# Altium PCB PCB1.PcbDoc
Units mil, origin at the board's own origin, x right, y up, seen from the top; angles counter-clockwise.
Board outline 4025 x 3055 mil, 2 copper layers (Top Layer, Bottom Layer); 6 components, 13 nets, 109 pads, 0 vias.
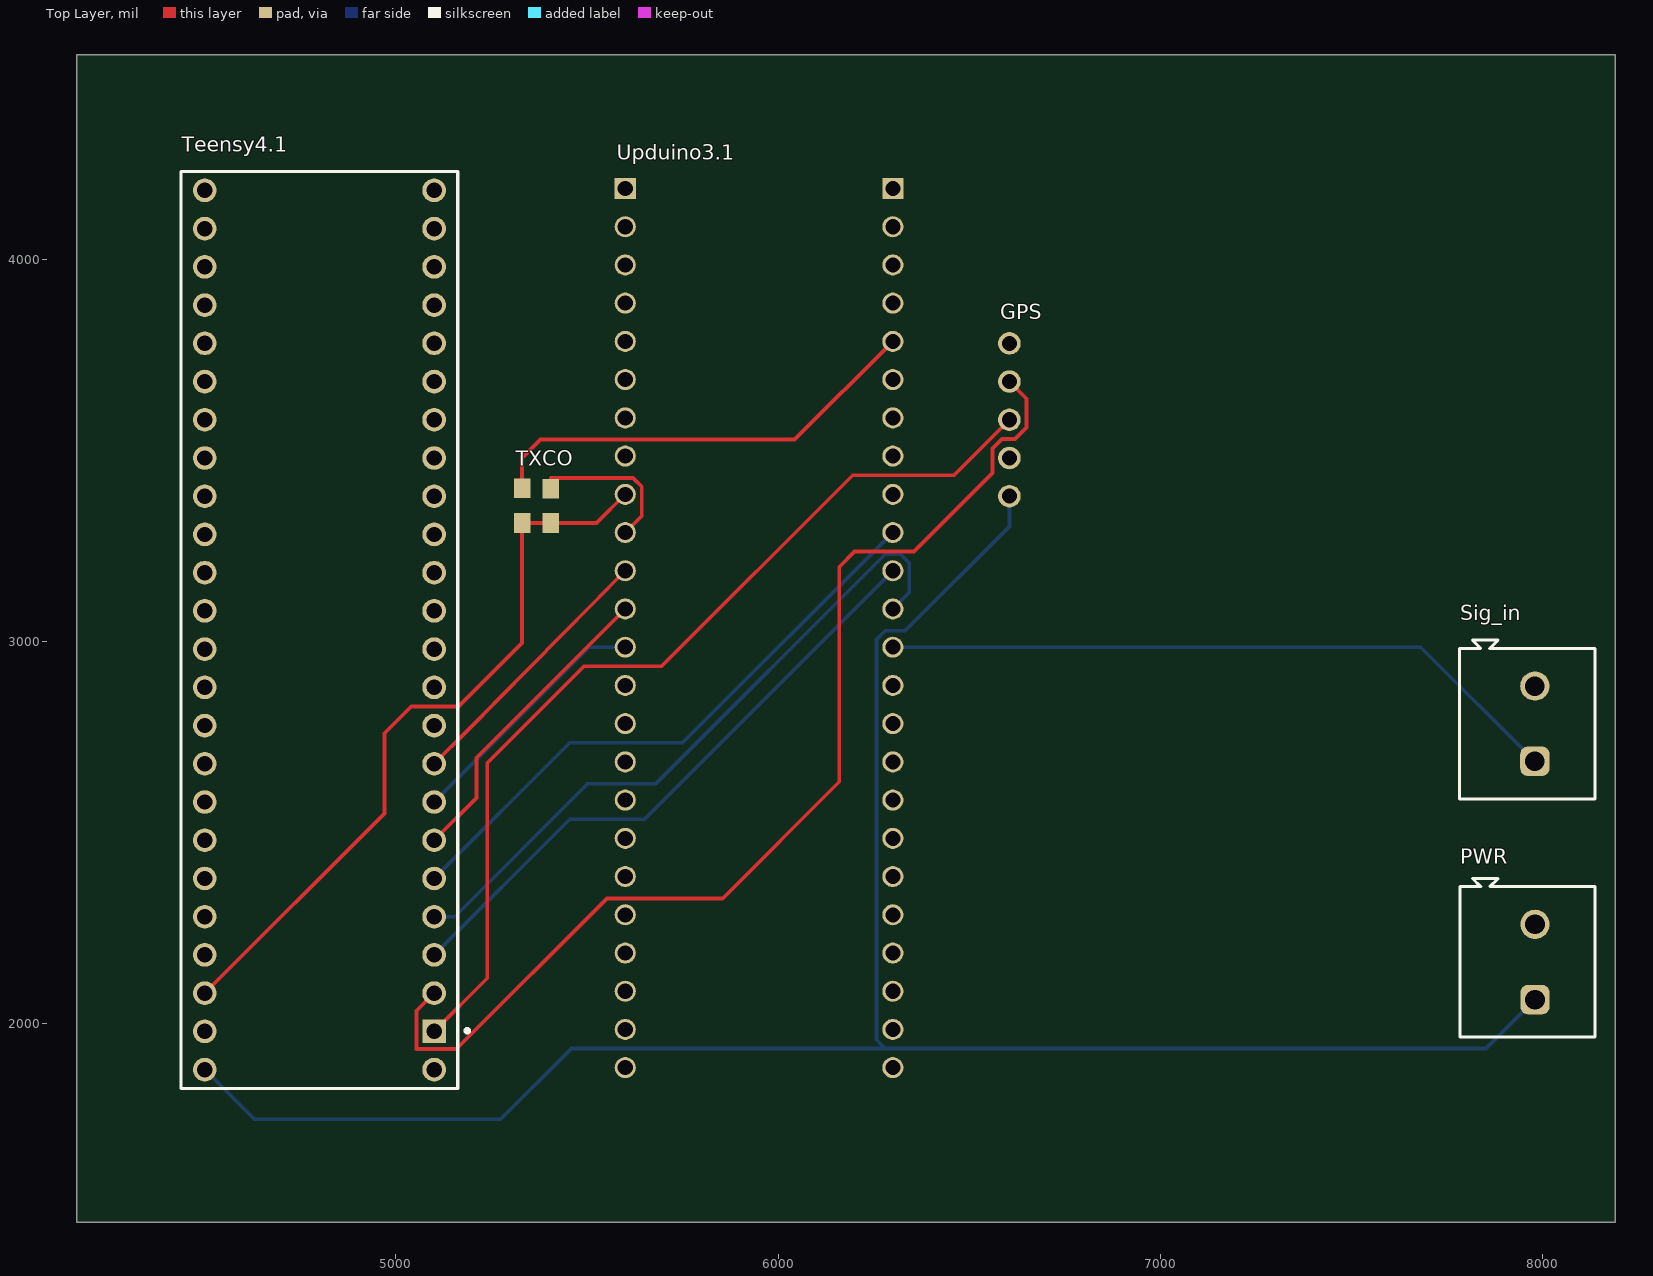
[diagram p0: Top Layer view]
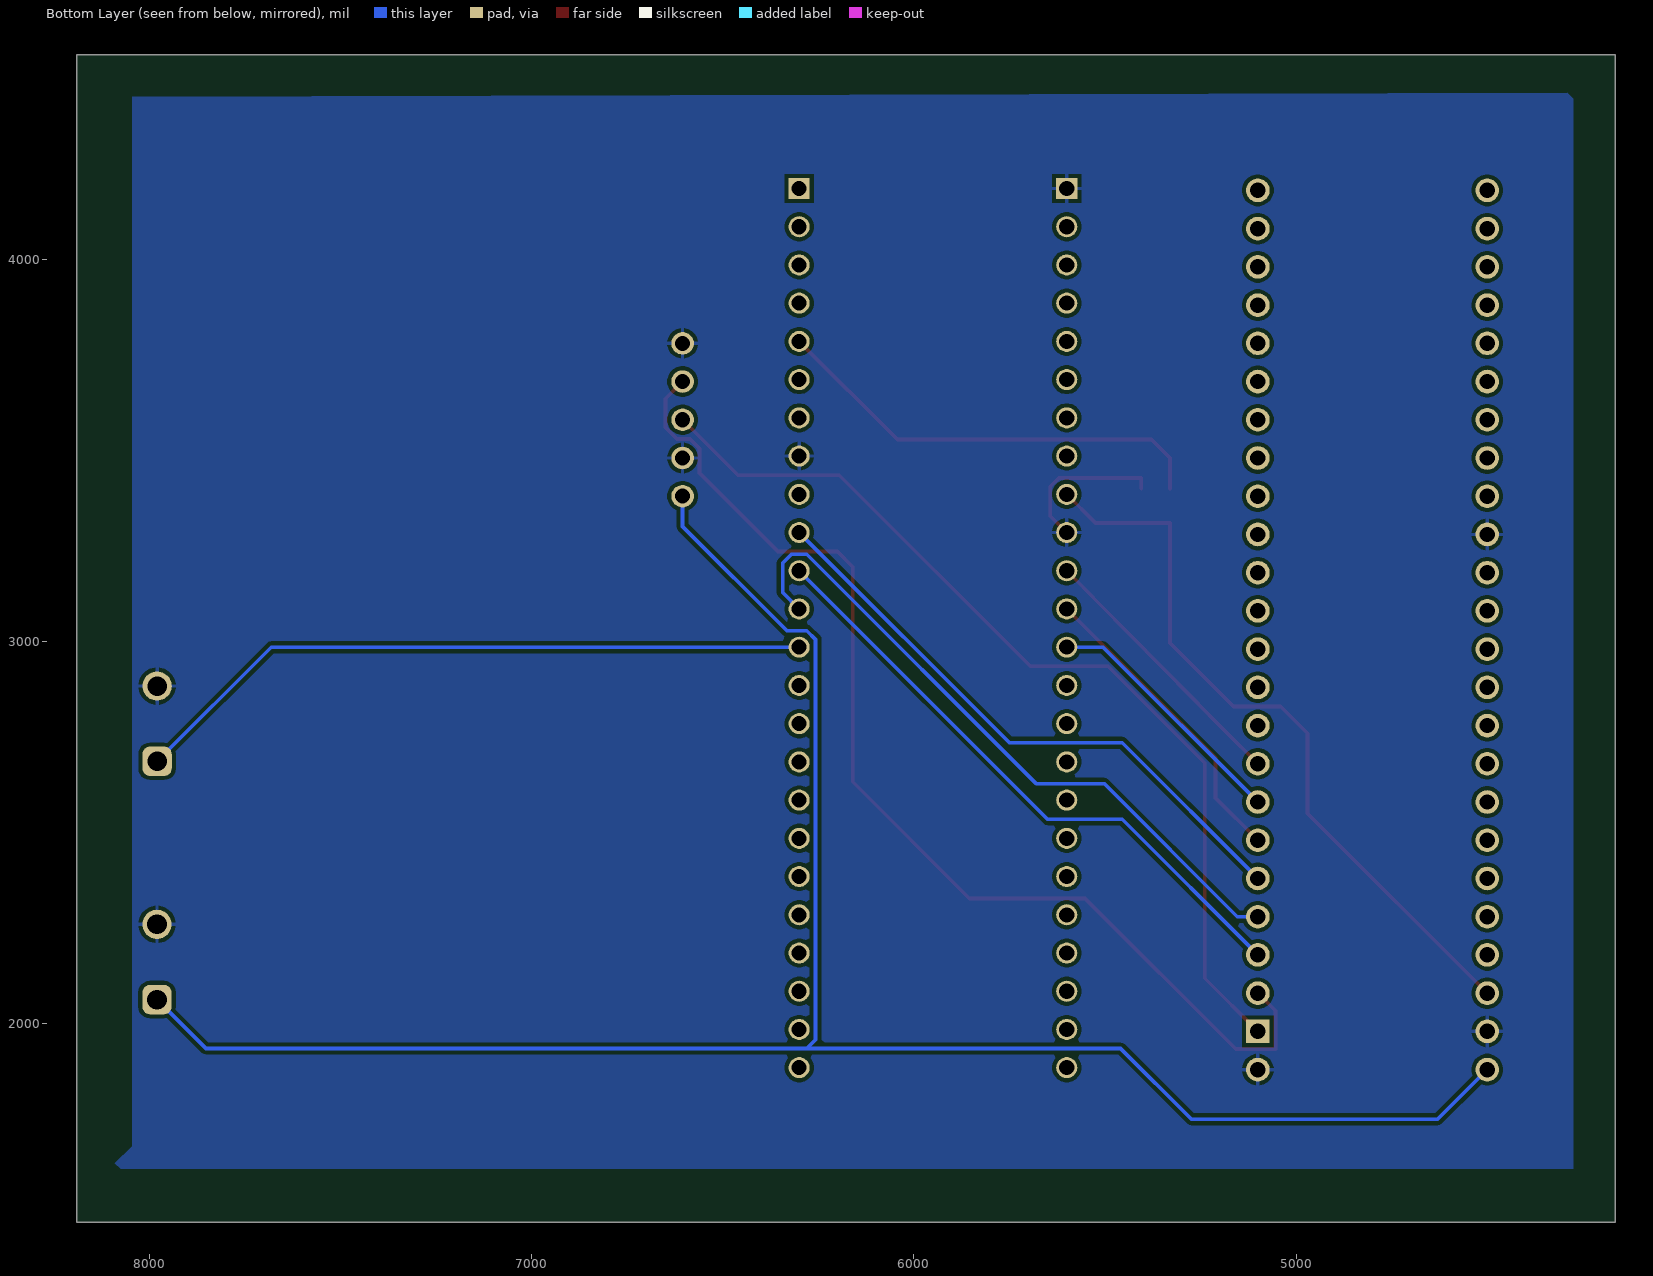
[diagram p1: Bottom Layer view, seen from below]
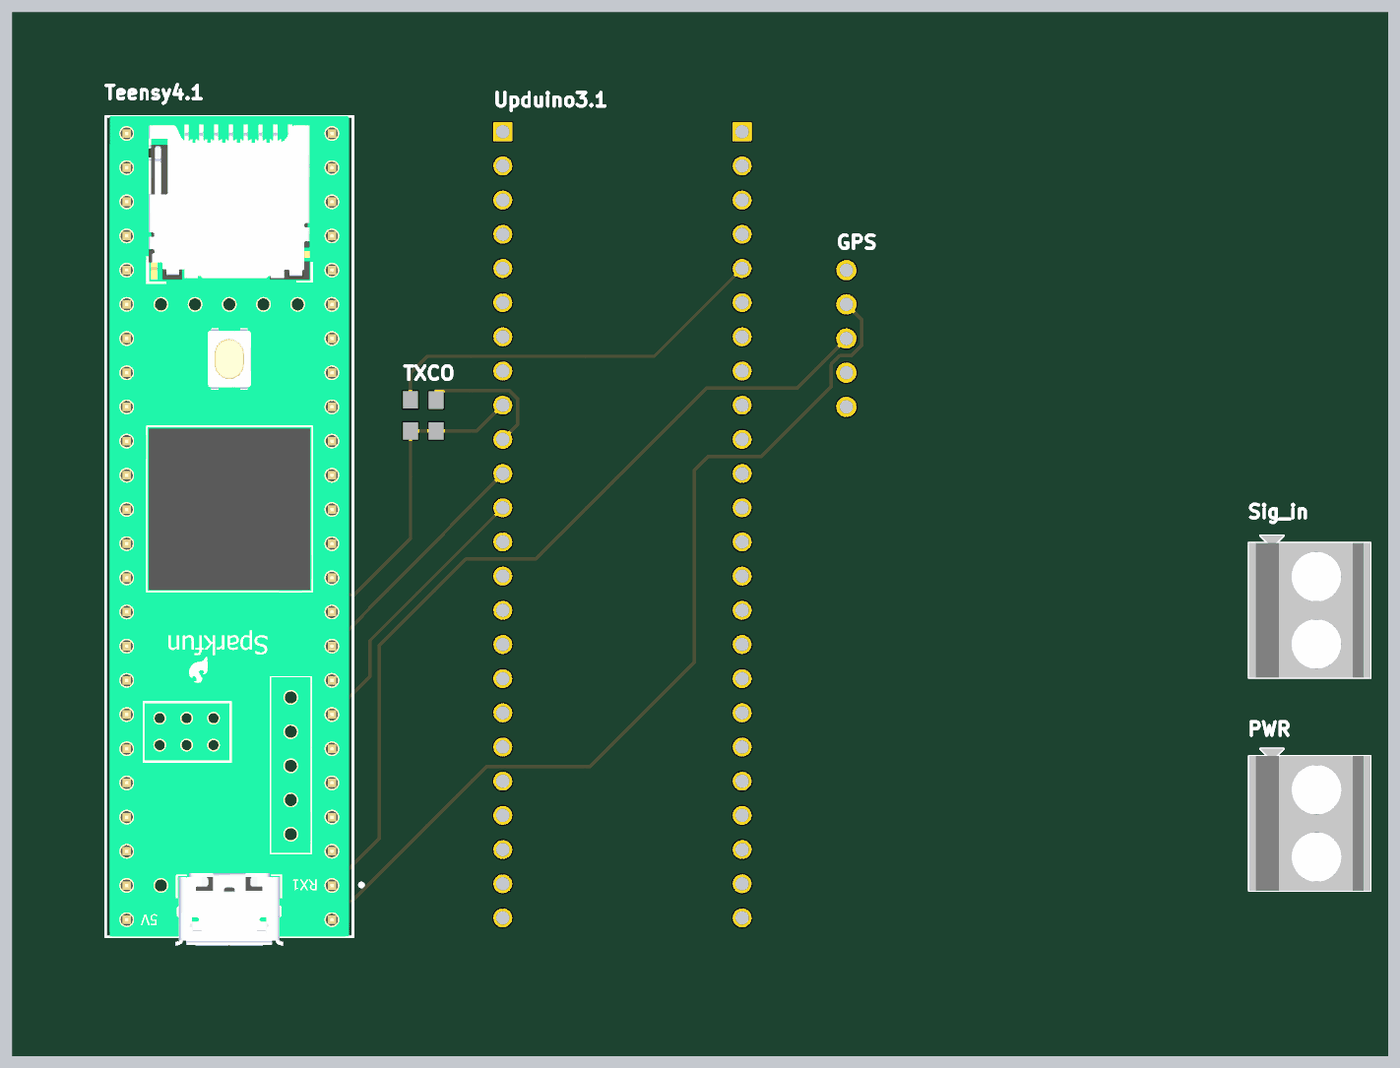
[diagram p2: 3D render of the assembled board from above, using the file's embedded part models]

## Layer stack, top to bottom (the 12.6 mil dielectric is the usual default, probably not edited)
Top Solder: solder mask 0.4, Solder Resist, Dk 3.5
Top Layer: signal copper 1.4
Dielectric 1: dielectric 12.6, FR-4, Dk 4.8
Bottom Layer: signal copper 1.4
Bottom Solder: solder mask 0.4, Solder Resist, Dk 3.5

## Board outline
4165,1480 8190,1480 8190,4535 4165,4535

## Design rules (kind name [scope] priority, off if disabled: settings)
Clearance [All] p1: gap=10 ignorepadtopadclearanceinfootprint=FALSE
PolygonConnect [All] p1: connectstyle=Relief reliefconductorwidth=10 reliefentries=4 polygonreliefangle="90 Angle" airgapwidth=10
RoutingVias [All] p1: holewidth=28 width=50 viastyle="Through Hole" minholewidth=28 minwidth=50 maxholewidth=28 maxwidth=50
SolderMaskExpansion [All] p1: expansion=4 istentingtop=FALSE
Width [All] p1: maxlimit=10 minlimit=10 preferedwidth=10
30 further rules are at their usual default settings.

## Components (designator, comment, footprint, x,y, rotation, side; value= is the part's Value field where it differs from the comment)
GPS "GPS_Module" GPS 6605,3380 r0 top
PWR "691134710002" 691134710002 7960.31,2161.57 r90 top
Sig_in "691134710002" 691134710002 7960,2785 r90 top
Teensy4.1 "DEV-16996" FP-DEV-16996-MFG 4800,3030 r90 top
TXCO "TXCO Clock" "TXCO CLOCK" 5405,3310 r90 top
Upduino3.1 "FPGA" UPDUINOV3.1 5600,1885 r0 top

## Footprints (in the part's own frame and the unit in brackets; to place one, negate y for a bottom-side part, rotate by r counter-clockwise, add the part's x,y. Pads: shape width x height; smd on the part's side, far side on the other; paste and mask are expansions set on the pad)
691134710002 [mm] "Serie 1347 - 5.00 mm_2 pins"
  rrect50% 1.95x1.95 hole 1.3: 1(-2.5,-0.5)
  round 1.95 hole 1.3: 2(2.5,-0.5)
  silkscreen extent -5,-4.5 5.55,4.5, body extent -5,-4.5 5.55,4.5, height 13.1
FP-DEV-16996-MFG [mm]
  rect 1.57x1.57 hole 1.02 paste-2539.97 mask+0: 0(-26.67,-7.62)
  round 1.57 hole 1.02 paste-2539.97 mask+0: 1(-24.13,-7.62) 2(-21.59,-7.62) 3(-19.05,-7.62) 4(-16.51,-7.62) 5(-13.97,-7.62) 6(-11.43,-7.62) 7(-8.89,-7.62) 8(-6.35,-7.62) 9(-3.81,-7.62) 10(-1.27,-7.62) 11(1.27,-7.62) 12(3.81,-7.62) 13(3.81,7.62) 14(1.27,7.62) 15(-1.27,7.62) 16(-3.81,7.62) 17(-6.35,7.62) 18(-8.89,7.62) 19(-11.43,7.62) 20(-13.97,7.62) 21(-16.51,7.62) 22(-19.05,7.62) 23(-21.59,7.62) 24(8.89,-7.62) 25(11.43,-7.62) 26(13.97,-7.62) 27(16.51,-7.62) 28(19.05,-7.62) 29(21.59,-7.62) 30(24.13,-7.62) 31(26.67,-7.62) 32(29.21,-7.62) 33(29.21,7.62) 34(26.67,7.62) 35(24.13,7.62) 36(21.59,7.62) 37(19.05,7.62) 38(16.51,7.62) 39(13.97,7.62) 40(11.43,7.62) 41(8.89,7.62) 42(-29.21,7.62) 43(-26.67,7.62) 44(-24.13,7.62) 45(6.35,7.62) 46(-29.21,-7.62) 47(6.35,-7.62)
  silkscreen extent -30.48,-9.95 30.48,9.19, body extent -30.58,-9.29 30.58,9.29, height 0.25
GPS [mm]
  round 1.5 hole 1: M1(0,0) M2(0,2.54) M3(0,5.08) M4(0,7.62) M5(0,10.16)
"TXCO CLOCK" [mm]
  rect 1.3x1.1 smd: M1(0,0) M2(2.286,0) M3(2.3,1.905) M4(0,1.9)
UPDUINOV3.1 [mm]
  round 1.4 hole 1: 1(0,0) 2(0,2.54) 3(0,5.08) 3v3(0,38.1) 4(0,7.62) 5(0,10.16) 6(0,12.7) 7(0,15.24) 8(0,17.78) 9(0,20.32) 10(0,22.86) 11(0,25.4) 13(17.78,33.02) 17(0,40.64) 18(17.78,27.94) 19(17.78,30.48) 20(17.78,48.26) 21(17.78,35.56) 22(0,53.34) 23(0,33.02) 25(0,30.48) 26(0,27.94) 27(17.78,5.08) 28(17.78,7.62) 29(17.78,10.16) 30(17.78,12.7) 31(17.78,15.24) 32(17.78,17.78) 33(17.78,20.32) 34(17.78,22.86) 35(17.78,25.4) 40(17.78,38.1) 42(17.78,43.18) 43(17.78,45.72) 44(0,48.26) 45(17.78,50.8) 46(17.78,53.34) 47(17.78,55.88) 50(17.78,0) 51(17.78,2.54) 52(0,55.88) 55(0,43.18) 56(0,45.72) 57(0,50.8) GND(0,35.56) GND(17.78,40.64)
  rect 1.4x1.4 hole 1: 48(17.78,58.42) GND(0,58.42)

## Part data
PWR Sig_in: library part CMP-1502-03295-3, "Wire-To-Board Terminal Block, 5mm Pitch, Horizontal, Screw, 2 Poles"
Teensy4.1: library part CMP-157412-000001-1, "TEENSY 4.1 (HEADERS)"

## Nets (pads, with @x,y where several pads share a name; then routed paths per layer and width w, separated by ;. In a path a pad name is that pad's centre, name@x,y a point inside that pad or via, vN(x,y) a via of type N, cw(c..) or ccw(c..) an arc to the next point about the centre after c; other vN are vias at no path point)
3v3: Teensy4.1.44 TXCO.M1 TXCO.M4 Upduino3.1.3v3 | length 1947.4
  Top Layer w10: Teensy4.1.44 4970,2550 4970,2760 5040,2830 5164,2830 5330.2,2996.2 TXCO.M4 TXCO.M1 5525,3310 Upduino3.1.3v3
5v: GPS.M1 PWR.1 Teensy4.1.42 | length 5292.7
  Bottom Layer w10: Teensy4.1.42 4630,1750 5274,1750 5459,1935 6280,1935 ; GPS.M1 6605,3301 6332,3028 6280,3028 6257,3005 6257,1958 6280,1935 ; PWR.1 7851.85,1935 6280,1935
clk: TXCO.M3 Upduino3.1.20 | length 1175.8
  Top Layer w10: TXCO.M3 5330,3480 5378,3528 6043,3528 Upduino3.1.20
cnt_enable: Teensy4.1.2 Upduino3.1.13 | length 1616.3
  Bottom Layer w10: Teensy4.1.2 5455,2535 5650,2535 Upduino3.1.13
done: Teensy4.1.5 Upduino3.1.25 | length 812.1
  Top Layer w10: Teensy4.1.5 5210.88,2590.88 5210.88,2695.88 Upduino3.1.25
freqOut: Teensy4.1.7 Upduino3.1.23 | length 710.7
  Top Layer w10: Teensy4.1.7 5187.09,2767.09 Upduino3.1.23
GND: GPS.M2 GPS.M5 PWR.2 Sig_in.2 Teensy4.1.43 Teensy4.1.45 Teensy4.1.46 TXCO.M2 Upduino3.1.GND | length 413.3
  Top Layer w10: TXCO.M2 5405,3428 5620,3428 5643,3405 5643,3328 Upduino3.1.GND@5600,3285
rst_n: Teensy4.1.4 Upduino3.1.21 | length 1574.9
  Bottom Layer w10: Teensy4.1.4 5455,2735 5750,2735 Upduino3.1.21
RX: GPS.M3 Teensy4.1.0 | length 2497.5
  Top Layer w10: Teensy4.1.0 5239,2119 5239,2682 5492,2935 5695,2935 6195,3435 6460,3435 GPS.M3
sclk: Teensy4.1.6 Upduino3.1.26 | length 667.8
  Bottom Layer w10: Teensy4.1.6 5505,2985 Upduino3.1.26
signal_in: Sig_in.1 Upduino3.1.18 | length 1803.3
  Bottom Layer w10: Upduino3.1.18 7681.26,2985 Sig_in.1
start_transmit: Teensy4.1.3 Upduino3.1.19 | length 1783
  Bottom Layer w10: Teensy4.1.3 5154,2280 5502,2628 5680,2628 6280,3228 6320,3228 6343,3205 6343,3128 Upduino3.1.19
TX: GPS.M4 Teensy4.1.1 | length 2939.9
  Top Layer w10: Teensy4.1.1 5054,2034 5054,1934 5158,1934 5552,2328 5855,2328 6160,2633 6160,3195 6200,3235 6355,3235 6560.47,3440.47 6560.47,3504.47 6586,3530 6620,3530 6650,3560 6650,3635 GPS.M4
pads on no net: Teensy4.1.8 Teensy4.1.9 Teensy4.1.10 Teensy4.1.11 Teensy4.1.12 Teensy4.1.13 Teensy4.1.14 Teensy4.1.15 Teensy4.1.16 Teensy4.1.17 Teensy4.1.18 Teensy4.1.19 Teensy4.1.20 Teensy4.1.21 Teensy4.1.22 Teensy4.1.23 Teensy4.1.24 Teensy4.1.25 Teensy4.1.26 Teensy4.1.27 Teensy4.1.28 Teensy4.1.29 Teensy4.1.30 Teensy4.1.31 Teensy4.1.32 Teensy4.1.33 Teensy4.1.34 Teensy4.1.35 Teensy4.1.36 Teensy4.1.37 Teensy4.1.38 Teensy4.1.39 Teensy4.1.40 Teensy4.1.41 Teensy4.1.47 Upduino3.1.1 Upduino3.1.2 Upduino3.1.3 Upduino3.1.4 Upduino3.1.5 Upduino3.1.6 Upduino3.1.7 Upduino3.1.8 Upduino3.1.9 Upduino3.1.10 Upduino3.1.11 Upduino3.1.17 Upduino3.1.22 Upduino3.1.27 Upduino3.1.28 Upduino3.1.29 Upduino3.1.30 Upduino3.1.31 Upduino3.1.32 Upduino3.1.33 Upduino3.1.34 Upduino3.1.35 Upduino3.1.40 Upduino3.1.42 Upduino3.1.43 Upduino3.1.44 Upduino3.1.45 Upduino3.1.46 Upduino3.1.47 Upduino3.1.48 Upduino3.1.50 Upduino3.1.51 Upduino3.1.52 Upduino3.1.55 Upduino3.1.56 Upduino3.1.57

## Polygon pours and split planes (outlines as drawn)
GND on Bottom Layer "GND_L02_P000" (solid, remove dead copper, pour order 0): 4290,4435 4275,4420 4275,1620 8075,1620 8090,1635 8045,1680 8045,4425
